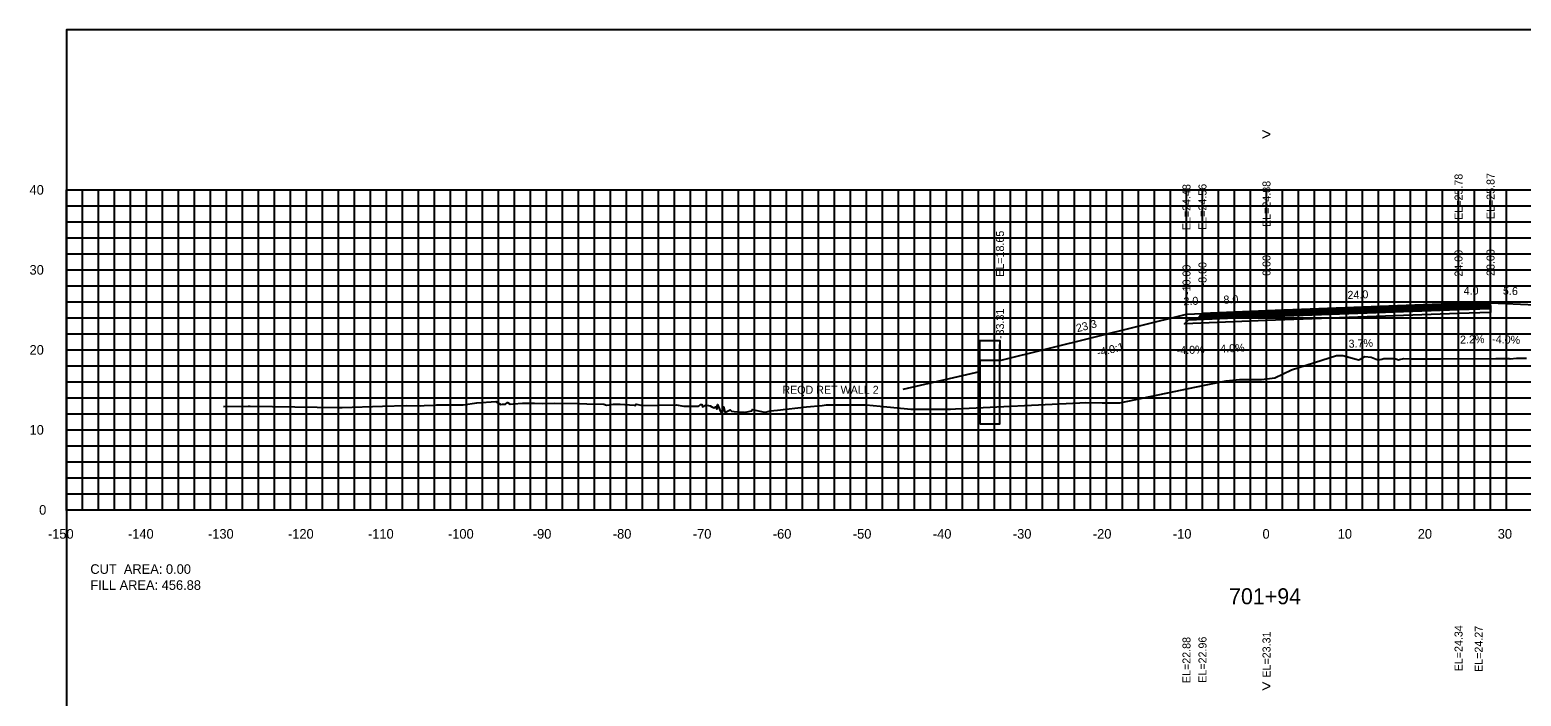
# Model space of a CAD drawing. Extents: x 1797518 to 1804843, y 248068 to 251132.
# Drawn here: x 1802136.4 to 1802322.8, y 250186.1 to 250269.4 of the extents above; entities that cross this region are included whole.
import ezdxf

# ---------------------------------------------------------------- set-up
doc = ezdxf.new("R2010")
doc.units = 0
for name, color, linetype in [('1', 7, 'Continuous'), ('10', 7, 'Continuous'), ('3', 7, 'Continuous'), ('31', 7, 'Continuous'), ('4', 7, 'Continuous'), ('60', 7, 'Continuous'), ('ANNO-TXT', 7, 'Continuous'), ('BASE', 7, 'Continuous'), ('CL-CNST', 7, 'Continuous'), ('Level 62', 7, 'Continuous'), ('LOWER BINDER', 7, 'Continuous'), ('M-ROADS', 7, 'Continuous'), ('UPPER BINDER', 7, 'Continuous'), ('WEARING', 7, 'Continuous')]:
    doc.layers.add(name, color=color, linetype=linetype)

msp = doc.modelspace()

# ---------------------------------------------------------------- linework, layer by layer
for p, q in [((1802315, 250235.21), (1802315, 250237.21)), ((1802319, 250235.3), (1802319, 250237.3)), ((1802281, 250233.91), (1802281, 250235.91)), ((1802283, 250233.99), (1802283, 250235.99)), ((1802291, 250234.31), (1802291, 250236.31)), ((1802257.69, 250228.09), (1802257.69, 250230.09))]:
    msp.add_line(p, q)
msp.add_lwpolyline([(1802141, 250079.43), (1802441, 250079.43), (1802441, 250269.43), (1802141, 250269.43)], close=True)
at = {"layer": '3'}
msp.add_line((1802245.59, 250224.5), (1802255.19, 250226.74), dxfattribs=at)
at = {"layer": '60'}
for p, q in [((1802140.94, 250249.43), (1802141, 250249.43)), ((1802141, 250209.43), (1802141, 250249.43)), ((1802140.94, 250239.43), (1802141, 250239.43)), ((1802140.94, 250229.43), (1802141, 250229.43)), ((1802140.94, 250219.43), (1802141, 250219.43)), ((1802140.94, 250209.43), (1802141, 250209.43)), ((1802141, 250209.43), (1802441, 250209.43)), ((1802141, 250209.37), (1802141, 250209.43)), ((1802151, 250209.37), (1802151, 250209.43)), ((1802161, 250209.37), (1802161, 250209.43)), ((1802171, 250209.37), (1802171, 250209.43)), ((1802181, 250209.37), (1802181, 250209.43)), ((1802191, 250209.37), (1802191, 250209.43)), ((1802201, 250209.37), (1802201, 250209.43)), ((1802211, 250209.37), (1802211, 250209.43)), ((1802221, 250209.37), (1802221, 250209.43)), ((1802231, 250209.37), (1802231, 250209.43)), ((1802241, 250209.37), (1802241, 250209.43)), ((1802251, 250209.37), (1802251, 250209.43)), ((1802261, 250209.37), (1802261, 250209.43)), ((1802271, 250209.37), (1802271, 250209.43)), ((1802281, 250209.37), (1802281, 250209.43)), ((1802291, 250209.37), (1802291, 250209.43)), ((1802301, 250209.37), (1802301, 250209.43)), ((1802311, 250209.37), (1802311, 250209.43)), ((1802321, 250209.37), (1802321, 250209.43))]:
    msp.add_line(p, q, dxfattribs=at)
at = {"layer": 'BASE'}
msp.add_lwpolyline([(1802281.25, 250233.2), (1802282.25, 250233.24), (1802291, 250233.59), (1802315, 250234.49), (1802319, 250234.58), (1802319, 250234.08), (1802315, 250233.99), (1802291, 250233.09), (1802280.73, 250232.68)], close=True, dxfattribs=at)
at = {"layer": 'CL-CNST'}
msp.add_lwpolyline([(1802257.69, 250228.09), (1802281, 250233.91), (1802283, 250233.99), (1802291, 250234.31), (1802315, 250235.21), (1802319, 250235.3), (1802324.6, 250235.07)], dxfattribs=at)
for points in [[(1802257.69, 250228.09), (1802255.19, 250228.09), (1802255.19, 250230.59), (1802257.69, 250230.59)], [(1802255.19, 250220.2), (1802257.69, 250220.2), (1802257.69, 250228.09), (1802255.19, 250228.09)]]:
    msp.add_lwpolyline(points, close=True, dxfattribs=at)
at = {"layer": 'Level 62'}
for p, q in [((1802141, 250249.43), (1802441, 250249.43)), ((1802141, 250209.43), (1802141, 250249.43)), ((1802143, 250209.43), (1802143, 250249.43)), ((1802145, 250209.43), (1802145, 250249.43)), ((1802147, 250209.43), (1802147, 250249.43)), ((1802149, 250209.43), (1802149, 250249.43)), ((1802151, 250209.43), (1802151, 250249.43)), ((1802153, 250209.43), (1802153, 250249.43)), ((1802155, 250209.43), (1802155, 250249.43)), ((1802157, 250209.43), (1802157, 250249.43)), ((1802159, 250209.43), (1802159, 250249.43)), ((1802161, 250209.43), (1802161, 250249.43)), ((1802163, 250209.43), (1802163, 250249.43)), ((1802165, 250209.43), (1802165, 250249.43)), ((1802167, 250209.43), (1802167, 250249.43)), ((1802169, 250209.43), (1802169, 250249.43)), ((1802171, 250209.43), (1802171, 250249.43)), ((1802173, 250209.43), (1802173, 250249.43)), ((1802175, 250209.43), (1802175, 250249.43)), ((1802177, 250209.43), (1802177, 250249.43)), ((1802179, 250209.43), (1802179, 250249.43)), ((1802181, 250209.43), (1802181, 250249.43)), ((1802183, 250209.43), (1802183, 250249.43)), ((1802185, 250209.43), (1802185, 250249.43)), ((1802187, 250209.43), (1802187, 250249.43)), ((1802189, 250209.43), (1802189, 250249.43)), ((1802191, 250209.43), (1802191, 250249.43)), ((1802193, 250209.43), (1802193, 250249.43)), ((1802195, 250209.43), (1802195, 250249.43)), ((1802197, 250209.43), (1802197, 250249.43)), ((1802199, 250209.43), (1802199, 250249.43)), ((1802201, 250209.43), (1802201, 250249.43)), ((1802203, 250209.43), (1802203, 250249.43)), ((1802205, 250209.43), (1802205, 250249.43)), ((1802207, 250209.43), (1802207, 250249.43)), ((1802209, 250209.43), (1802209, 250249.43)), ((1802211, 250209.43), (1802211, 250249.43)), ((1802213, 250209.43), (1802213, 250249.43)), ((1802215, 250209.43), (1802215, 250249.43)), ((1802217, 250209.43), (1802217, 250249.43)), ((1802219, 250209.43), (1802219, 250249.43)), ((1802221, 250209.43), (1802221, 250249.43)), ((1802223, 250209.43), (1802223, 250249.43)), ((1802225, 250209.43), (1802225, 250249.43)), ((1802227, 250209.43), (1802227, 250249.43)), ((1802229, 250209.43), (1802229, 250249.43)), ((1802231, 250209.43), (1802231, 250249.43)), ((1802233, 250209.43), (1802233, 250249.43)), ((1802235, 250209.43), (1802235, 250249.43)), ((1802237, 250209.43), (1802237, 250249.43)), ((1802239, 250209.43), (1802239, 250249.43)), ((1802241, 250209.43), (1802241, 250249.43)), ((1802243, 250209.43), (1802243, 250249.43)), ((1802245, 250209.43), (1802245, 250249.43)), ((1802247, 250209.43), (1802247, 250249.43)), ((1802249, 250209.43), (1802249, 250249.43)), ((1802251, 250209.43), (1802251, 250249.43)), ((1802253, 250209.43), (1802253, 250249.43)), ((1802255, 250209.43), (1802255, 250249.43)), ((1802257, 250209.43), (1802257, 250249.43)), ((1802259, 250209.43), (1802259, 250249.43)), ((1802261, 250209.43), (1802261, 250249.43)), ((1802263, 250209.43), (1802263, 250249.43)), ((1802265, 250209.43), (1802265, 250249.43)), ((1802267, 250209.43), (1802267, 250249.43)), ((1802269, 250209.43), (1802269, 250249.43)), ((1802271, 250209.43), (1802271, 250249.43)), ((1802273, 250209.43), (1802273, 250249.43)), ((1802275, 250209.43), (1802275, 250249.43)), ((1802277, 250209.43), (1802277, 250249.43)), ((1802279, 250209.43), (1802279, 250249.43)), ((1802281, 250209.43), (1802281, 250249.43)), ((1802283, 250209.43), (1802283, 250249.43)), ((1802285, 250209.43), (1802285, 250249.43)), ((1802287, 250209.43), (1802287, 250249.43)), ((1802289, 250209.43), (1802289, 250249.43)), ((1802291, 250209.43), (1802291, 250249.43)), ((1802293, 250209.43), (1802293, 250249.43)), ((1802295, 250209.43), (1802295, 250249.43)), ((1802297, 250209.43), (1802297, 250249.43)), ((1802299, 250209.43), (1802299, 250249.43)), ((1802301, 250209.43), (1802301, 250249.43)), ((1802303, 250209.43), (1802303, 250249.43)), ((1802305, 250209.43), (1802305, 250249.43)), ((1802307, 250209.43), (1802307, 250249.43)), ((1802309, 250209.43), (1802309, 250249.43)), ((1802311, 250209.43), (1802311, 250249.43)), ((1802313, 250209.43), (1802313, 250249.43)), ((1802315, 250209.43), (1802315, 250249.43)), ((1802317, 250209.43), (1802317, 250249.43)), ((1802319, 250209.43), (1802319, 250249.43)), ((1802321, 250209.43), (1802321, 250249.43)), ((1802141, 250247.43), (1802441, 250247.43)), ((1802141, 250245.43), (1802441, 250245.43)), ((1802141, 250243.43), (1802441, 250243.43)), ((1802141, 250241.43), (1802441, 250241.43)), ((1802141, 250239.43), (1802441, 250239.43)), ((1802141, 250237.43), (1802441, 250237.43)), ((1802141, 250235.43), (1802441, 250235.43)), ((1802141, 250233.43), (1802441, 250233.43)), ((1802141, 250231.43), (1802441, 250231.43)), ((1802141, 250229.43), (1802441, 250229.43)), ((1802141, 250227.43), (1802441, 250227.43)), ((1802141, 250225.43), (1802441, 250225.43)), ((1802141, 250223.43), (1802441, 250223.43)), ((1802141, 250221.43), (1802441, 250221.43)), ((1802141, 250219.43), (1802441, 250219.43)), ((1802141, 250217.43), (1802441, 250217.43)), ((1802141, 250215.43), (1802441, 250215.43)), ((1802141, 250213.43), (1802441, 250213.43)), ((1802141, 250211.43), (1802441, 250211.43)), ((1802141, 250209.43), (1802441, 250209.43))]:
    msp.add_line(p, q, dxfattribs=at)
at = {"layer": 'LOWER BINDER'}
for points in [[(1802291, 250233.78), (1802315, 250234.68), (1802319, 250234.77), (1802319, 250234.58), (1802315, 250234.49), (1802291, 250233.59), (1802282.25, 250233.24), (1802282.45, 250233.44)], [(1802291, 250233.97), (1802315, 250234.87), (1802319, 250234.96), (1802319, 250234.77), (1802315, 250234.68), (1802291, 250233.78), (1802282.45, 250233.44), (1802282.65, 250233.64)]]:
    msp.add_lwpolyline(points, close=True, dxfattribs=at)
at = {"layer": 'M-ROADS'}
msp.add_lwpolyline([(1802160.65, 250222.35), (1802163.72, 250222.41), (1802163.98, 250222.4), (1802175.12, 250222.24), (1802175.47, 250222.24), (1802180.53, 250222.4), (1802183.49, 250222.48), (1802185.26, 250222.45), (1802185.71, 250222.46), (1802186.9, 250222.5), (1802187.32, 250222.56), (1802188.29, 250222.56), (1802189.25, 250222.56), (1802190.6, 250222.56), (1802192.29, 250222.79), (1802194.66, 250222.96), (1802195.31, 250222.62), (1802195.52, 250222.63), (1802195.71, 250222.63), (1802195.81, 250222.66), (1802195.88, 250222.65), (1802196.12, 250222.84), (1802196.45, 250222.63), (1802196.9, 250222.69), (1802198.03, 250222.76), (1802199.52, 250222.75), (1802200.55, 250222.74), (1802202.03, 250222.76), (1802205.13, 250222.71), (1802206.07, 250222.7), (1802208.18, 250222.64), (1802208.5, 250222.52), (1802208.85, 250222.57), (1802209.37, 250222.66), (1802210.2, 250222.64), (1802210.82, 250222.62), (1802211.95, 250222.53), (1802212.15, 250222.49), (1802212.23, 250222.64), (1802213, 250222.47), (1802217.21, 250222.56), (1802218.18, 250222.38), (1802219.47, 250222.4), (1802219.91, 250222.38), (1802219.95, 250222.35), (1802220.08, 250222.43), (1802220.25, 250222.61), (1802220.36, 250222.62), (1802220.42, 250222.62), (1802220.51, 250222.35), (1802220.52, 250222.3), (1802220.97, 250222.54), (1802221.03, 250222.53), (1802221.46, 250222.42), (1802221.67, 250222.3), (1802221.97, 250222.19), (1802222.19, 250222.31), (1802222.28, 250222.35), (1802222.29, 250222.02), (1802222.33, 250222.44), (1802222.38, 250222.58), (1802222.75, 250221.71), (1802222.86, 250221.55), (1802223, 250221.54), (1802223.13, 250222.29), (1802223.31, 250221.67), (1802223.39, 250221.63), (1802223.95, 250221.94), (1802224.14, 250221.78), (1802224.48, 250221.73), (1802225.64, 250221.63), (1802225.8, 250221.61), (1802225.82, 250221.64), (1802225.83, 250221.62), (1802225.88, 250221.63), (1802226.68, 250221.82), (1802226.73, 250221.99), (1802228.24, 250221.65), (1802228.31, 250221.61), (1802228.37, 250221.63), (1802228.98, 250221.8), (1802229.89, 250221.9), (1802233.51, 250222.29), (1802235.46, 250222.49), (1802235.95, 250222.54), (1802236.65, 250222.54), (1802238.34, 250222.54), (1802238.49, 250222.54), (1802240.71, 250222.54), (1802240.95, 250222.54), (1802242.7, 250222.38), (1802246.53, 250222.01), (1802247.05, 250222), (1802248.94, 250222), (1802249.27, 250222.01), (1802250.05, 250222.01), (1802251.52, 250222.01), (1802252.15, 250222.05), (1802267.68, 250222.82), (1802268.41, 250222.83), (1802270.47, 250222.8), (1802270.78, 250222.8), (1802272.67, 250222.82), (1802283.26, 250225.02), (1802285.94, 250225.56), (1802287.63, 250225.74), (1802289.01, 250225.74), (1802290.39, 250225.74), (1802292.04, 250225.94), (1802294.11, 250226.93), (1802299.75, 250228.73), (1802300.56, 250228.73), (1802302.22, 250228.26), (1802302.5, 250228.17), (1802302.63, 250228.21), (1802303.3, 250228.58), (1802304.08, 250228.53), (1802304.9, 250228.2), (1802305, 250228.17), (1802305.41, 250228.28), (1802305.68, 250228.34), (1802305.84, 250228.34), (1802306.94, 250228.34), (1802307.16, 250228.29), (1802307.49, 250228.17), (1802307.64, 250228.21), (1802308.16, 250228.35), (1802309, 250228.3), (1802309.41, 250228.3), (1802312.76, 250228.32), (1802319.68, 250228.36), (1802320.52, 250228.34), (1802320.93, 250228.34), (1802321.31, 250228.34), (1802321.46, 250228.31), (1802322.23, 250228.4), (1802322.4, 250228.4), (1802323.49, 250228.39)], dxfattribs=at)
at = {"layer": 'UPPER BINDER'}
msp.add_lwpolyline([(1802319, 250234.96), (1802319, 250235.15), (1802315, 250235.06), (1802291, 250234.16), (1802282.85, 250233.84), (1802282.65, 250233.64), (1802291, 250233.97), (1802315, 250234.87)], close=True, dxfattribs=at)
at = {"layer": 'WEARING'}
msp.add_lwpolyline([(1802319, 250235.15), (1802319, 250235.3), (1802315, 250235.21), (1802291, 250234.31), (1802283, 250233.99), (1802282.85, 250233.84), (1802291, 250234.16), (1802315, 250235.06)], close=True, dxfattribs=at)

# ---------------------------------------------------------------- texts
msp.add_text('-4.0:1', height=1, rotation=14.0362).set_placement((1802269.95, 250228.57))
at = {"layer": '1'}
msp.add_text('701+94', height=2, dxfattribs=at).set_placement((1802286.32, 250197.63))
at = {"layer": '10'}
for s, p in [('-150', (1802138.7, 250205.83)), ('-140', (1802148.7, 250205.83)), ('-130', (1802158.7, 250205.83)), ('-120', (1802168.7, 250205.83)), ('-110', (1802178.7, 250205.83)), ('-100', (1802188.7, 250205.83)), ('-90', (1802199.3, 250205.83)), ('-80', (1802209.3, 250205.83)), ('-70', (1802219.3, 250205.83)), ('-60', (1802229.3, 250205.83)), ('-50', (1802239.3, 250205.83)), ('-40', (1802249.3, 250205.83)), ('-30', (1802259.3, 250205.83)), ('-20', (1802269.3, 250205.83)), ('-10', (1802279.3, 250205.83)), ('0', (1802290.5, 250205.83)), ('10', (1802299.9, 250205.83)), ('20', (1802309.9, 250205.83)), ('30', (1802319.9, 250205.83))]:
    msp.add_text(s, height=1.2, dxfattribs=at).set_placement(p)
at = {"layer": '3'}
for s, p in [('EL=25.87', (1802319.5, 250245.77)), ('EL=24.48', (1802281.5, 250244.39)), ('EL=24.56', (1802283.5, 250244.42)), ('EL=24.88', (1802291.5, 250244.79)), ('EL=25.78', (1802315.5, 250245.68)), ('EL=18.65', (1802258.19, 250238.56)), ('-8.00', (1802283.5, 250237.36)), ('0.00', (1802291.5, 250238.68)), ('24.00', (1802315.5, 250238.58)), ('28.00', (1802319.5, 250238.67)), ('-10.00', (1802281.5, 250236.29)), ('-33.31', (1802258.19, 250230.79)), ('EL=23.31', (1802291.5, 250188.46)), ('EL=24.34', (1802315.5, 250189.25)), ('EL=24.27', (1802318.02, 250189.17)), ('EL=22.88', (1802281.5, 250187.78)), ('EL=22.96', (1802283.5, 250187.82))]:
    msp.add_text(s, height=1, rotation=90, dxfattribs=at).set_placement(p)
msp.add_text('REQD RET WALL 2', height=1, dxfattribs=at).set_placement((1802230.49, 250223.94))
at = {"layer": '31'}
for s, p in [('40', (1802136.4, 250248.83)), ('30', (1802136.4, 250238.83)), ('20', (1802136.4, 250228.83)), ('10', (1802136.4, 250218.83)), ('0', (1802137.6, 250208.83))]:
    msp.add_text(s, height=1.2, dxfattribs=at).set_placement(p)
at = {"layer": '4'}
for s, rotation, p in [('24.0', 2.1378, (1802301.14, 250235.79)), ('4.0', 1.2603, (1802315.65, 250236.32)), ('5.6', 357.6958, (1802320.54, 250236.34)), ('2.0', 2.2906, (1802280.64, 250235)), ('8.0', 2.2906, (1802285.64, 250235.2)), ('23.3', 14.0362, (1802267.35, 250231.63)), ('2.2%', 1.2603, (1802315.2, 250230.21)), ('-4.0%', 357.6958, (1802319.19, 250230.29)), ('-4.0%', 2.2906, (1802279.79, 250228.86)), ('-4.0%', 2.2906, (1802284.79, 250229.06)), ('3.7%', 2.1378, (1802301.28, 250229.69))]:
    msp.add_text(s, height=1, rotation=rotation, dxfattribs=at).set_placement(p)
at = {"layer": '60'}
for s, height, p in [('>', 1.5, (1802290.39, 250255.66)), ('-', 0.0001, (1802141, 250209.43)), ('>', 1.5, (1802290.39, 250186.68))]:
    msp.add_text(s, height=height, dxfattribs=at).set_placement(p)
at = {"layer": 'ANNO-TXT'}
for s, p in [('CUT  AREA: 0.00', (1802144, 250201.43)), ('FILL AREA: 456.88', (1802144, 250199.43))]:
    msp.add_text(s, height=1.2, dxfattribs=at).set_placement(p)

doc.saveas('drawing.dxf')
